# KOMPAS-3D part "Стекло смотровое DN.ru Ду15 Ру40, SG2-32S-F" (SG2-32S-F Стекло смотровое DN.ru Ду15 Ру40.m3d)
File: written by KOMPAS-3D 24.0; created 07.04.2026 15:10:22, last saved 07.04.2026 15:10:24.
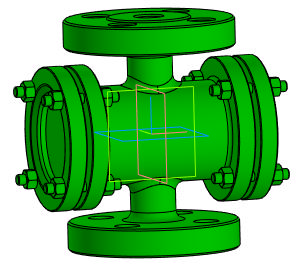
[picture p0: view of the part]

Document properties: Автор: Main; Полное имя файла: D:\DN.ru Аутсерс\Стекло смотровое DN.ru\SG2-32S-F Стекло смотровое DN.ru Ду15 Ру40\SG2-32S-F Стекло смотровое DN.ru Ду15 Ру40.m3d

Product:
- Body: Тело 1  | qty 1
    Масса: 3.175709
- Part/product: Стекло смотровое DN.ru Ду15 Ру40  | designation SG2-32S-F
    Масса: 4
    Раздел спецификации: Прочие изделия
    Примечание: D500-00103

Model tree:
1. Операция без истории:1

Expressions: SG2-32S-F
